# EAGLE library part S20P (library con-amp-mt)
AMP MT CONNECTOR
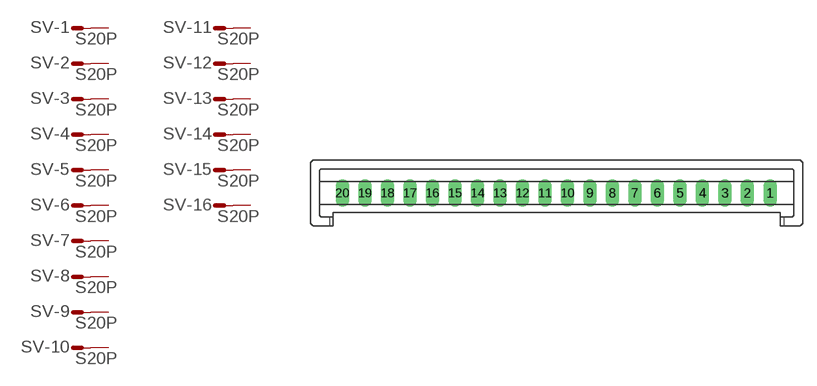
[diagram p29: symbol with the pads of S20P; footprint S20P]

Designator prefix SV; gates -1=M -2=M -3=M -4=M -5=M -6=M -7=M -8=M -9=M -10=M -11=M -12=M -13=M -14=M -15=M -16=M -17=M -18=M -19=M -20=M

## S20P (OC_FARNELL: unknown; OC_NEWARK: unknown)  [S20P]
1  -1:S  pas
2  -2:S  pas
3  -3:S  pas
4  -4:S  pas
5  -5:S  pas
6  -6:S  pas
7  -7:S  pas
8  -8:S  pas
9  -9:S  pas
10  -10:S  pas
11  -11:S  pas
12  -12:S  pas
13  -13:S  pas
14  -14:S  pas
15  -15:S  pas
16  -16:S  pas
17  -17:S  pas
18  -18:S  pas
19  -19:S  pas
20  -20:S  pas

## Footprint S20P (pad centres in mm)
AMP MT CONNECTOR
drill 1.016 long: 1 23.75,0; 2 21.25,0; 3 18.75,0; 4 16.25,0; 5 13.75,0; 6 11.25,0; 7 8.75,0; 8 6.25,0; 9 3.75,0; 10 1.25,0; 11 -1.25,0; 12 -3.75,0; 13 -6.25,0; 14 -8.75,0; 15 -11.25,0; 16 -13.75,0; 17 -16.25,0; 18 -18.75,0; 19 -21.25,0; 20 -23.75,0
